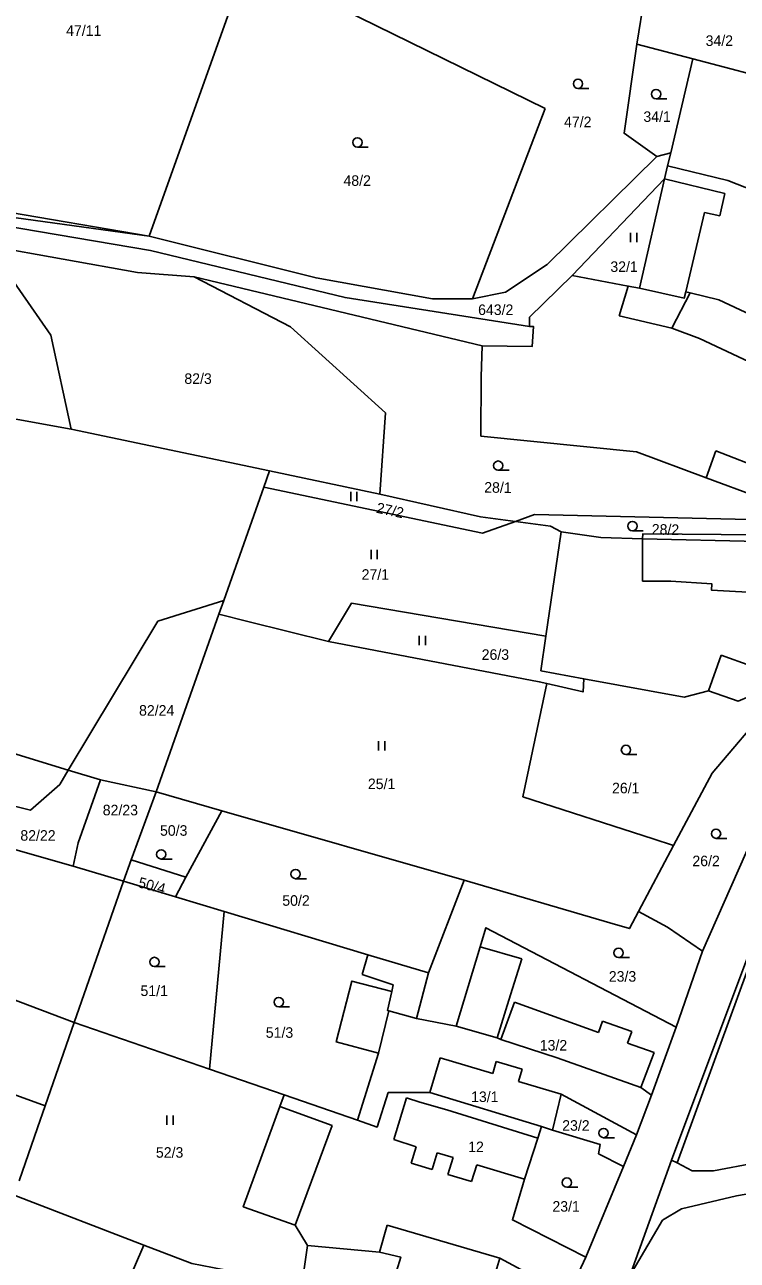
# Model space of a CAD drawing. Extents: x -744566 to -741843, y -1128407 to -1126744.
# Drawn here: x -743048.6 to -742933.7, y -1127545.1 to -1127345.9 of the extents above; entities that cross this region are included whole.
import ezdxf

# ---------------------------------------------------------------- set-up
doc = ezdxf.new("R2010")
doc.units = 0
for name, color, linetype in [('Hranice parcel', 7, 'Continuous'), ('Parcelní čísla', 7, 'Continuous'), ('Vnitřní kresba', 7, 'Continuous'), ('Značky kultur', 7, 'Continuous')]:
    doc.layers.add(name, color=color, linetype=linetype)

msp = doc.modelspace()

# ---------------------------------------------------------------- linework, layer by layer
at = {"layer": 'Hranice parcel'}
for p, q in [((-742947.95, -1127337.31), (-742949.84, -1127349.03)), ((-743014.16, -1127339.69), (-743028.55, -1127379.99)), ((-742940.83, -1127351.4), (-742949.84, -1127349.03)), ((-742940.83, -1127351.4), (-742944.36, -1127366.56)), ((-742964.65, -1127359.41), (-742976.38, -1127390.08)), ((-742946.62, -1127367.12), (-742944.36, -1127366.56)), ((-742944.36, -1127366.56), (-742944.92, -1127368.65)), ((-742944.92, -1127368.65), (-742945.39, -1127370.73)), ((-743100.68, -1127370.05), (-743028.55, -1127379.99)), ((-742960.31, -1127386.35), (-742945.39, -1127370.73)), ((-742945.39, -1127370.73), (-742949.42, -1127388.37)), ((-743028.55, -1127379.99), (-743066.9, -1127373.47)), ((-743021.3, -1127386.55), (-742974.81, -1127397.66)), ((-743009.13, -1127417.82), (-743041.1, -1127411.11)), ((-743010.06, -1127420.45), (-743009.13, -1127417.82)), ((-743009.13, -1127417.82), (-742991.33, -1127421.56)), ((-743016.5, -1127438.72), (-743010.06, -1127420.45)), ((-742962.06, -1127427.67), (-742964.54, -1127444.49)), ((-743017.29, -1127440.95), (-743016.5, -1127438.72)), ((-743017.29, -1127440.95), (-743027.39, -1127469.59)), ((-742968.23, -1127470.39), (-742964.4, -1127452.09)), ((-743036.38, -1127467.62), (-743041.59, -1127466.09)), ((-743027.39, -1127469.59), (-743036.38, -1127467.62)), ((-743027.39, -1127469.59), (-743031.43, -1127480.55)), ((-743027.39, -1127469.59), (-743016.81, -1127472.62)), ((-742947.25, -1127477.16), (-742968.23, -1127470.39)), ((-743016.81, -1127472.62), (-743022.6, -1127483.32)), ((-743016.81, -1127472.62), (-742977.71, -1127483.81)), ((-742949.6, -1127488.85), (-742943.93, -1127478.23)), ((-742943.93, -1127478.23), (-742947.25, -1127477.16)), ((-743031.43, -1127480.55), (-743032.69, -1127483.96)), ((-743031.43, -1127480.55), (-743022.6, -1127483.32)), ((-743032.69, -1127483.96), (-743040.81, -1127481.55)), ((-743032.69, -1127483.96), (-743040.66, -1127506.77)), ((-743024.31, -1127486.49), (-743032.69, -1127483.96)), ((-743022.6, -1127483.32), (-743024.31, -1127486.49)), ((-742977.71, -1127483.81), (-742983.49, -1127498.74)), ((-742954.21, -1127490.71), (-742977.71, -1127483.81)), ((-743024.31, -1127486.49), (-743016.42, -1127488.87)), ((-743018.83, -1127514.29), (-743016.42, -1127488.87)), ((-742944.28, -1127528.98), (-742929.86, -1127490.53)), ((-742943.52, -1127507.49), (-742939.27, -1127495.28)), ((-742983.49, -1127498.74), (-742985.43, -1127506.13)), ((-743045.31, -1127520.19), (-743040.66, -1127506.77)), ((-743040.66, -1127506.77), (-743018.83, -1127514.29)), ((-742979.03, -1127507.34), (-742985.43, -1127506.13)), ((-742943.52, -1127507.49), (-742947.48, -1127518.45)), ((-743018.83, -1127514.29), (-743006.77, -1127518.44)), ((-742994.94, -1127522.52), (-743006.77, -1127518.44)), ((-742983.25, -1127518.03), (-742989.99, -1127518.04)), ((-742965.23, -1127523.55), (-742983.25, -1127518.03)), ((-742949.93, -1127524.86), (-742947.48, -1127518.45)), ((-742965.23, -1127523.55), (-742963.44, -1127524.1)), ((-742952.01, -1127529.96), (-742949.93, -1127524.86)), ((-742952.01, -1127529.96), (-742956.04, -1127527.94)), ((-742958.07, -1127544.59), (-742952.01, -1127529.96)), ((-742950.97, -1127547.61), (-742944.28, -1127528.98)), ((-743029.41, -1127542.64), (-743050.32, -1127534.62)), ((-742933.8, -1127534.7), (-742942.64, -1127536.81)), ((-742928.77, -1127533.84), (-742933.8, -1127534.7)), ((-743029.41, -1127542.64), (-743044.5, -1127577.53)), ((-743003.69, -1127547.61), (-743002.99, -1127542.69)), ((-742960.97, -1127550.69), (-742958.07, -1127544.59))]:
    msp.add_line(p, q, dxfattribs=at)
for points in [[(-743014.16, -1127339.69), (-742997.35, -1127343.38), (-742964.65, -1127359.41)], [(-742923.23, -1127346.19), (-742925.69, -1127355.37), (-742940.83, -1127351.4)], [(-742949.84, -1127349.03), (-742951.91, -1127363.4), (-742946.62, -1127367.12)], [(-742976.38, -1127390.08), (-742971.06, -1127389.03), (-742964.3, -1127384.57), (-742946.62, -1127367.12)], [(-742893.95, -1127387.18), (-742935.19, -1127371.02), (-742944.92, -1127368.65)], [(-742967.2, -1127394.53), (-742996.94, -1127389.89), (-743028.35, -1127382.31), (-743100.68, -1127370.05)], [(-743028.55, -1127379.99), (-743001.6, -1127386.7), (-742982.84, -1127390.07), (-742976.38, -1127390.08)], [(-743021.3, -1127386.55), (-743030.41, -1127385.86), (-743054.48, -1127381.54)], [(-743054.48, -1127381.54), (-743044.4, -1127395.97), (-743041.1, -1127411.11)], [(-742991.33, -1127421.56), (-742990.42, -1127408.45), (-743005.74, -1127394.62), (-743021.3, -1127386.55)], [(-742967.2, -1127394.53), (-742967.2, -1127393.06), (-742960.31, -1127386.35)], [(-742949.42, -1127388.37), (-742951.24, -1127388.03), (-742960.31, -1127386.35)], [(-743041.1, -1127411.11), (-743084.2, -1127403.32), (-743167.67, -1127389.27)], [(-742949.42, -1127388.37), (-742942.2, -1127389.97), (-742941.95, -1127388.95), (-742941.26, -1127389.12), (-742936.65, -1127390.26), (-742908.27, -1127403.53)], [(-742974.81, -1127397.66), (-742966.76, -1127397.79), (-742966.54, -1127394.52), (-742967.2, -1127394.53)], [(-742928.65, -1127422.67), (-742930.23, -1127422.08), (-742938.69, -1127418.93), (-742949.94, -1127414.75), (-742975.01, -1127412.21), (-742974.95, -1127402.66), (-742974.81, -1127397.66)], [(-742969.45, -1127425.98), (-742974.74, -1127427.87), (-743010.06, -1127420.45)], [(-742969.45, -1127425.98), (-742975.09, -1127425.22), (-742991.33, -1127421.56)], [(-743180.36, -1127424.17), (-743158.88, -1127430.74), (-743108.99, -1127445.38), (-743041.59, -1127466.09)], [(-742969.45, -1127425.98), (-742966.36, -1127424.88), (-742929.36, -1127425.71)], [(-742962.06, -1127427.67), (-742963.79, -1127426.75), (-742969.45, -1127425.98)], [(-742929.93, -1127428.12), (-742948.91, -1127427.98), (-742948.92, -1127428.77), (-742955.66, -1127428.57), (-742962.06, -1127427.67)], [(-743040.81, -1127481.55), (-743071.4, -1127472.85), (-743155.92, -1127450.8), (-743202.45, -1127431.75)], [(-743183.58, -1127433.05), (-743149.11, -1127446.12), (-743119.92, -1127454.41), (-743047.66, -1127472.53), (-743042.97, -1127468.39), (-743041.59, -1127466.09)], [(-743041.59, -1127466.09), (-743027.12, -1127442.06), (-743016.5, -1127438.72)], [(-742964.54, -1127444.49), (-742995.91, -1127439.17), (-742999.6, -1127445.32)], [(-742999.6, -1127445.32), (-743012.61, -1127442.11), (-743017.29, -1127440.95)], [(-742964.54, -1127444.49), (-742965.34, -1127450.06), (-742958.39, -1127451.34)], [(-743040.66, -1127506.77), (-743056.44, -1127500.82), (-743133.85, -1127476.88), (-743160.99, -1127467.42), (-743199.57, -1127452.71), (-743214.09, -1127445.46)], [(-742964.4, -1127452.09), (-742965.61, -1127451.81), (-742999.6, -1127445.32)], [(-742958.39, -1127451.34), (-742958.54, -1127453.46), (-742964.4, -1127452.09)], [(-742958.39, -1127451.34), (-742942.2, -1127454.33), (-742938.29, -1127453.29), (-742933.5, -1127454.97), (-742931.72, -1127454.21), (-742928.29, -1127455.5)], [(-743045.31, -1127520.19), (-743104.96, -1127498.48), (-743151.66, -1127482.51), (-743195.56, -1127465.33), (-743218.68, -1127453.92)], [(-742943.93, -1127478.23), (-742937.72, -1127466.57), (-742928.29, -1127455.5)], [(-743040.81, -1127481.55), (-743039.98, -1127477.77), (-743036.38, -1127467.62)], [(-742939.27, -1127495.28), (-742928.77, -1127471.57), (-742930.03, -1127470.75)], [(-743016.42, -1127488.87), (-742993.26, -1127495.85), (-742983.49, -1127498.74)], [(-742949.6, -1127488.85), (-742951.07, -1127491.63), (-742954.21, -1127490.71)], [(-742939.27, -1127495.28), (-742944.9, -1127491.4), (-742949.6, -1127488.85)], [(-742979.03, -1127507.34), (-742975.14, -1127494.55), (-742974.21, -1127491.49), (-742943.52, -1127507.49)], [(-742985.43, -1127506.13), (-742989.89, -1127504.88), (-742990.08, -1127504.83), (-742989.41, -1127501.75), (-742995.84, -1127500.07), (-742998.35, -1127509.89), (-742991.56, -1127511.71), (-742994.94, -1127522.52)], [(-742944.28, -1127528.98), (-742943.36, -1127529.4), (-742940.91, -1127530.67), (-742937.49, -1127530.65), (-742930.66, -1127529.38), (-742920.21, -1127526.66), (-742917.02, -1127525.28), (-742914.34, -1127523.24), (-742912.34, -1127520.62), (-742910.6, -1127517.69), (-742907.48, -1127511.22), (-742905.69, -1127508.04), (-742903.28, -1127501.66)], [(-742947.48, -1127518.45), (-742949.22, -1127517.23), (-742962.69, -1127512.44), (-742971.81, -1127509.49), (-742972.41, -1127509.22), (-742979.03, -1127507.34)], [(-743006.77, -1127518.44), (-743007.45, -1127520.31), (-743013.35, -1127536.47), (-743005, -1127539.46), (-743002.99, -1127542.69)], [(-742989.99, -1127518.04), (-742991.77, -1127523.61), (-742994.94, -1127522.52)], [(-742963.44, -1127524.1), (-742962.06, -1127518.33), (-742949.93, -1127524.86)], [(-743049.5, -1127532.27), (-743046.55, -1127523.76), (-743045.31, -1127520.19)], [(-742958.07, -1127544.59), (-742969.92, -1127538.58), (-742968.01, -1127532.03), (-742965.83, -1127525.39), (-742965.23, -1127523.55)], [(-742956.04, -1127527.94), (-742955.76, -1127526.44), (-742963.44, -1127524.1)], [(-742942.64, -1127536.81), (-742945.7, -1127538.65), (-742950.97, -1127547.61)], [(-743005.01, -1127551.2), (-743016.66, -1127546.56), (-743021.68, -1127545.63), (-743029.41, -1127542.64)], [(-743002.99, -1127542.69), (-742991.4, -1127543.81), (-742987.95, -1127544.57), (-742988.63, -1127546.87), (-742973.89, -1127551.23), (-742971.94, -1127544.76), (-742960.97, -1127550.69)]]:
    msp.add_lwpolyline(points, dxfattribs=at)
at = {"layer": 'Vnitřní kresba'}
for p, q in [((-742945.39, -1127370.73), (-742935.66, -1127373.12)), ((-742936.47, -1127376.72), (-742935.66, -1127373.12)), ((-742941.95, -1127388.95), (-742938.92, -1127376.14)), ((-742938.92, -1127376.14), (-742936.47, -1127376.72)), ((-742952.69, -1127392.81), (-742951.24, -1127388.03)), ((-742944.23, -1127394.84), (-742941.26, -1127389.12)), ((-742952.69, -1127392.81), (-742944.23, -1127394.84)), ((-742944.23, -1127394.84), (-742939.73, -1127396.48)), ((-742939.73, -1127396.48), (-742923.25, -1127404.22)), ((-742938.69, -1127418.93), (-742937.11, -1127414.59)), ((-742937.11, -1127414.59), (-742928.64, -1127417.89)), ((-742948.97, -1127435.6), (-742948.92, -1127428.77)), ((-742948.92, -1127428.77), (-742930.18, -1127429.19)), ((-742948.97, -1127435.6), (-742944.4, -1127435.62)), ((-742938.29, -1127453.29), (-742936.28, -1127447.55)), ((-742936.28, -1127447.55), (-742931.49, -1127449.23)), ((-742943.36, -1127529.4), (-742929.27, -1127490.78)), ((-742975.14, -1127494.55), (-742968.39, -1127496.47)), ((-742994.2, -1127499.03), (-742993.26, -1127495.85)), ((-742970.5, -1127503.16), (-742968.39, -1127496.47)), ((-742994.2, -1127499.03), (-742989.17, -1127500.66)), ((-742989.41, -1127501.75), (-742989.17, -1127500.66)), ((-742991.56, -1127511.71), (-742989.89, -1127504.88)), ((-742972.41, -1127509.22), (-742970.5, -1127503.16)), ((-742971.81, -1127509.49), (-742969.62, -1127503.47)), ((-742969.62, -1127503.47), (-742956.03, -1127508.38)), ((-742956.03, -1127508.38), (-742955.38, -1127506.56)), ((-742955.38, -1127506.56), (-742950.68, -1127508.23)), ((-742951.35, -1127510.07), (-742950.68, -1127508.23)), ((-742951.35, -1127510.07), (-742947.07, -1127511.61)), ((-742983.25, -1127518.03), (-742981.6, -1127512.47)), ((-742981.6, -1127512.47), (-742973.1, -1127514.99)), ((-742949.22, -1127517.23), (-742947.07, -1127511.61)), ((-742973.1, -1127514.99), (-742972.53, -1127513.06)), ((-742972.53, -1127513.06), (-742968.35, -1127514.3)), ((-742968.94, -1127516.27), (-742968.35, -1127514.3)), ((-742968.94, -1127516.27), (-742962.06, -1127518.33)), ((-743007.45, -1127520.31), (-742999.03, -1127523.38)), ((-742989.07, -1127525.61), (-742987.02, -1127518.91)), ((-742987.02, -1127518.91), (-742984.85, -1127519.61)), ((-742984.85, -1127519.61), (-742980.49, -1127520.84)), ((-742980.49, -1127520.84), (-742965.83, -1127525.39)), ((-743005, -1127539.46), (-742999.03, -1127523.38)), ((-742989.07, -1127525.61), (-742985.46, -1127526.79)), ((-742986.28, -1127529.44), (-742985.46, -1127526.79)), ((-742982.9, -1127530.47), (-742982.08, -1127527.77)), ((-742982.08, -1127527.77), (-742979.51, -1127528.51)), ((-742980.35, -1127531.26), (-742979.51, -1127528.51)), ((-742986.28, -1127529.44), (-742982.9, -1127530.47)), ((-742976.56, -1127532.4), (-742975.66, -1127529.7)), ((-742975.66, -1127529.7), (-742968.01, -1127532.03)), ((-742980.35, -1127531.26), (-742976.56, -1127532.4)), ((-742991.4, -1127543.81), (-742990.15, -1127539.46)), ((-742990.15, -1127539.46), (-742971.94, -1127544.76))]:
    msp.add_line(p, q, dxfattribs=at)
msp.add_lwpolyline([(-742944.4, -1127435.62), (-742937.77, -1127436.02), (-742937.83, -1127437.05), (-742929.04, -1127437.56), (-742928.98, -1127436.55), (-742925.07, -1127436.78)], dxfattribs=at)
at = {"layer": 'Značky kultur'}
for p, q in [((-742959.353, -1127356.16), (-742957.603, -1127356.16)), ((-742946.753, -1127357.82), (-742945.003, -1127357.82)), ((-742994.943, -1127365.62), (-742993.193, -1127365.62)), ((-742950.861, -1127380.96), (-742950.861, -1127379.46)), ((-742949.86, -1127380.96), (-742949.86, -1127379.46)), ((-742972.233, -1127417.73), (-742970.483, -1127417.73)), ((-742996.011, -1127422.7), (-742996.011, -1127421.2)), ((-742995.01, -1127422.7), (-742995.01, -1127421.2)), ((-742950.573, -1127427.47), (-742948.823, -1127427.47)), ((-742992.731, -1127432.05), (-742992.731, -1127430.55)), ((-742991.73, -1127432.05), (-742991.73, -1127430.55)), ((-742984.961, -1127445.9), (-742984.961, -1127444.4)), ((-742983.96, -1127445.9), (-742983.96, -1127444.4)), ((-742991.521, -1127462.88), (-742991.521, -1127461.38)), ((-742990.52, -1127462.88), (-742990.52, -1127461.38)), ((-742951.613, -1127463.56), (-742949.863, -1127463.56)), ((-742937.083, -1127477.07), (-742935.333, -1127477.07)), ((-743026.603, -1127480.4), (-743024.853, -1127480.4)), ((-743004.913, -1127483.57), (-743003.163, -1127483.57)), ((-742952.803, -1127496.28), (-742951.053, -1127496.28)), ((-743027.683, -1127497.75), (-743025.933, -1127497.75)), ((-743007.633, -1127504.22), (-743005.883, -1127504.22)), ((-743025.681, -1127523.28), (-743025.681, -1127521.78)), ((-743024.68, -1127523.28), (-743024.68, -1127521.78)), ((-742955.233, -1127525.33), (-742953.483, -1127525.33)), ((-742961.143, -1127533.31), (-742959.393, -1127533.31))]:
    msp.add_line(p, q, dxfattribs=at)
for centre in [(-742959.353, -1127355.41), (-742946.753, -1127357.07), (-742994.943, -1127364.87), (-742972.233, -1127416.98), (-742950.573, -1127426.72), (-742951.613, -1127462.81), (-742937.083, -1127476.32), (-743026.603, -1127479.65), (-743004.913, -1127482.82), (-742952.803, -1127495.53), (-743027.683, -1127497), (-743007.633, -1127503.47), (-742955.233, -1127524.58), (-742961.143, -1127532.56)]:
    msp.add_circle(centre, 0.75, dxfattribs=at)

# ---------------------------------------------------------------- texts
at = {"layer": 'Parcelní čísla'}
for s, p in [('47/11', (-743041.94, -1127347.69)), ('34/2', (-742938.761, -1127349.31)), ('47/2', (-742961.601, -1127362.41)), ('34/1', (-742948.801, -1127361.56)), ('48/2', (-742997.191, -1127371.87)), ('32/1', (-742954.131, -1127385.75)), ('643/2', (-742975.47, -1127392.69)), ('82/3', (-743022.861, -1127403.8)), ('27/1', (-742994.261, -1127435.38)), ('26/3', (-742974.891, -1127448.29)), ('82/24', (-743030.17, -1127457.29)), ('25/1', (-742993.251, -1127469.13)), ('26/1', (-742953.861, -1127469.81)), ('82/23', (-743036.03, -1127473.36)), ('50/3', (-743026.79, -1127476.65)), ('82/22', (-743049.32, -1127477.45)), ('26/2', (-742940.901, -1127481.56)), ('50/2', (-743007.061, -1127487.94)), ('23/3', (-742954.381, -1127500.18)), ('51/1', (-743029.941, -1127502.49)), ('51/3', (-743009.721, -1127509.23)), ('13/2', (-742965.521, -1127511.28)), ('13/1', (-742976.601, -1127519.58)), ('23/2', (-742961.901, -1127524.21)), ('52/3', (-743027.451, -1127528.56)), ('12', (-742977.072, -1127527.66)), ('23/1', (-742963.481, -1127537.26))]:
    msp.add_text(s, height=1.7, dxfattribs=at).set_placement(p)
for s, rotation, p in [('28/1', 359, (-742974.495, -1127421.32)), ('27/2', 348, (-742991.998, -1127424.555)), ('28/2', 359, (-742947.465, -1127428.09)), ('50/4', 345, (-743030.439, -1127484.931))]:
    msp.add_text(s, height=1.7, rotation=rotation, dxfattribs=at).set_placement(p)

doc.saveas('drawing.dxf')
